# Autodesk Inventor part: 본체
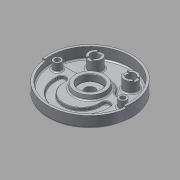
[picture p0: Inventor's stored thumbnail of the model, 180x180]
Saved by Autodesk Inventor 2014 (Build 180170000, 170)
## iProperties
Created: 2015-06
Part Number: 본체
Material: 알루미늄 6061
Document SubType Name: Modeling
Designer: MYHOME
Density: 2.71 g/cm^3
Appearance: 알루미늄 - 평지
Mass: 1071.11 g
Surface Area: 1034.48 cm^2
Volume: 395.243 cm^3
Author: MYHOME
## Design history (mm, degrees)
sketch "스케치1"
  geometry: C1 r 95 at (0, 0); 1 further point
  constraints: 1 centre point, 1 coincident
  dimensions: "d0" = 190 diameter of C1
extrude "돌출1" new body sketch "스케치1" distance "d1" = 32; taper "d2" = 0 deg
sketch "스케치2"
  geometry: C1 r 95 at (0, 0) reference
sketch "스케치3"
  geometry: C1 r 95 at (0, 0) reference; C2 r 90 at (0, 0)
  constraints: 1 centre point, 1 coincident
  dimensions: "d3" = 180 diameter of C2
extrude "돌출2" cut sketch "스케치3" distance "d4" = 25; taper "d5" = 0 deg
sketch "스케치4"
  geometry: C1 r 90 at (0, 0) reference; C2 r 15 at (-40, 52); C3 r 15 at (40, 52)
  constraints: 2 centre point
  dimensions: "d6" = 30 diameter of C2; "d7" = 30 diameter of C3; "d8" = 52 vertical distance of C1.centre C2.centre; "d9" = 52 vertical distance of C1.centre C3.centre; "d10" = 80 distance of C3.centre C2.centre; "d11" = 40 horizontal distance of C1.centre C2.centre
extrude "돌출3" join sketch "스케치4" distance "d12" = 25; taper "d13" = 0 deg
sketch "스케치5"
  geometry: C1 r 15 at (0, 0) reference; C2 r 15 at (80, 0) reference; C3 r 10 at (0, 0); C4 r 10 at (80, 0); 1 further point
  constraints: 2 centre point, 2 coincident
  dimensions: "d14" = 20 diameter of C3; "d15" = 20 diameter of C4
extrude "돌출4" cut sketch "스케치5" stored distance "d16" = 25; taper "d17" = 0 deg
sketch "스케치6"
  geometry: L1 (-6, 13.748)-(-6, -13.748); L2 (6, 13.748)-(6, -13.748); L3 (66.252, 6)-(93.748, 6); L4 (66.252, -6)-(93.748, -6); C1 r 10 at (0, 0) reference; C2 r 10 at (80, 0) reference; A1 r 15 centre (0, 0) between (-6, 13.748) and (6, 13.748) reference; A2 r 15 centre (80, 0) between (66.252, 6) and (66.252, -6) reference; 1 further point
  constraints: 8 end point, 8 point on circle, 2 parallel, 1 perpendicular, 1 vertical
  dimensions: "d18" = 12 distance between parallel lines of L2 L1; "d19" = 6 distance from line of L2 C1.centre; "d20" = 12 distance between parallel lines of L4 L3; "d21" = 6 distance from line of L3 C2.centre
extrude "돌출5" cut sketch "스케치6" distance "d22" = 3; taper "d23" = 0 deg
sketch "스케치7"
  geometry: L1 (-88.566, 16)-(-38.833, 16); L2 (38.833, 16)-(88.566, 16); C1 r 90 at (0, 0) reference; A1 r 90 centre (0, 0) between (-88.566, 16) and (88.566, 16) reference; A2 r 42 centre (0, 0) between (38.833, 16) and (-38.833, 16)
  constraints: 4 end point, 4 point on circle, 2 horizontal, 1 centre point, 1 coincident
  dimensions: "d24" = 16 vertical distance of L2.end A1.centre; "d25" = 84 diameter of A2; "d26" = 16 distance from line of A1.centre L1
extrude "돌출6" join sketch "스케치7" distance "d27" = 7; taper "d28" = 0 deg
sketch "스케치8"
  geometry: C1 r 9 at (-74, 0); C2 r 9 at (74, 0); A1 r 90 centre (0, 0) between (-88.566, 16) and (88.566, 16) reference
  constraints: 2 centre point, 2 horizontal alignment
  dimensions: "d29" = 18 diameter of C1; "d30" = 18 diameter of C2; "d31" = 148 distance of C2.centre C1.centre; "d32" = 74 distance of C2.centre A1.centre
extrude "돌출7" join sketch "스케치8" distance "d33" = 14; taper "d34" = 0 deg
sketch "스케치9"
  geometry: C1 r 35 at (0, 0); A1 r 42 centre (0, 0) between (38.833, 16) and (-38.833, 16) reference
  constraints: 1 centre point, 1 coincident
  dimensions: "d35" = 70 diameter of C1
extrude "돌출8" join sketch "스케치9" distance "d36" = 10; taper "d37" = -10 deg
sketch "스케치10"
  geometry: C1 r 33.237 at (0, 0) reference; C2 r 25 at (0, 0)
  constraints: 1 centre point, 1 coincident
  dimensions: "d38" = 50 diameter of C2
extrude "돌출9" cut sketch "스케치10" distance "d39" = 15; taper "d40" = 0 deg
sketch "스케치11"
  geometry: C1 r 25 at (0, 0) reference; C2 r 11.5 at (0, 0)
  constraints: 1 centre point, 1 coincident
  dimensions: "d41" = 23 diameter of C2
extrude "돌출10" cut sketch "스케치11" stored distance "d42" = 15; taper "d43" = 0 deg
sketch "스케치15"
  geometry: L1 (-38.833, 16)-(-88.566, 16) reference; L2 (-59, -14)-(-59, -19); L3 (-41, -14)-(-41, -19); L4 (41, -19)-(41, -14); L5 (59, -14)-(59, -19); C1 r 35 at (0, 0) reference; A1 r 9 centre (-50, -14) between (-41, -14) and (-59, -14); A2 r 9 centre (50, -14) between (59, -14) and (41, -14); A3 r 41 centre (0, -19) between (-40.992, -18.18) and (41, -19); A4 r 59 centre (0, -19) between (-58.988, -17.82) and (59, -19); 1 further point
  constraints: 10 point on circle, 8 end point, 4 centre point, 4 tangent, 3 parallel, 1 coincident, 1 perpendicular, 1 vertical alignment
  dimensions: "d64" = 9 radius of A1; "d65" = 9 radius of A2; "d66" = 14 vertical distance of C1.centre A1.centre; "d67" = 14 vertical distance of C1.centre A2.centre; "d68" = 100 distance of A2.centre A1.centre; "d69" = 50 horizontal distance of A1.centre C1.centre; "d70" = 19 distance of point (0, -19) C1.centre; "d72" = 59 radius of A4; "d73" = 41 radius of A3
extrude "돌출12" cut sketch "스케치15" distance "d74" = 7; taper "d75" = 0 deg
fillet "모깎기1" dims "d76" = 1
sketch "스케치16"
  geometry: C1 r 9 at (0, 0) reference; C2 r 9 at (148, 0) reference; C3 r 5.5 at (0, 0); C4 r 5.5 at (148, 0); 1 further point
  constraints: 2 centre point, 2 coincident
  dimensions: "d77" = 11 diameter of C3; "d78" = 11 diameter of C4
extrude "돌출13" cut sketch "스케치16" stored distance "d79" = 7; taper "d80" = 0 deg
sketch "스케치17"
  geometry: C1 r 5.5 at (74, 0) reference; C2 r 5.5 at (-74, 0) reference
hole "구멍1" sketch "스케치17" at (-74, 0), (74, 0) diameter "d81" = 18; stored, may be unused: countersink angle "d85" = 90 deg, drill point angle "d87" = 0 deg; dims "d82" = 6, "d83" = 4, "d84" = 2, "d86" = 11
fillet "모깎기2" dims "d88" = 10
node "작업 평면1"
sketch "스케치20"
  geometry: L1 (0, 0)-(-89.124, -12.526); L2 (0, 0)-(89.124, -12.526); L3 (-95, 0)-(95, 0); L4 (89.124, -12.526)-(94.075, -13.221); L5 (-89.124, -12.526)-(-94.075, -13.221); A1 r 90 centre (0, 0) between (89.124, -12.526) and (-89.124, -12.526) reference; A2 r 95 centre (0, 0) between (-94.075, -13.221) and (-95, 0) reference
  constraints: 10 end point, 6 point on circle, 2 collinear, 1 horizontal, 1 midpoint
  dimensions: "d97" = 8 deg angle of L2 L3; "d98" = 8 deg angle of L1 L3
extrude "돌출14" cut sketch "스케치20" distance "d99" = 5; taper "d100" = 0 deg
fillet "모깎기3" dims "d101" = 3
fillet "모깎기4" dims "d102" = 3
fillet "모깎기5" dims "d103" = 3
fillet "모깎기6" dims "d104" = 3
fillet "모깎기7" dims "d105" = 3
fillet "모깎기8" dims "d106" = 3
fillet "모깎기9" dims "d107" = 5
fillet "모깎기10" dims "d108" = 0.3
fillet "모깎기11" dims "d112" = 3
sketch "스케치21"
  geometry: C1 r 90 at (0, 0) reference; C2 r 68 at (0, 0)
  constraints: 1 centre point, 1 coincident, 1 other
  dimensions: "d114" = 136 diameter of C2
feature "엠보싱1" sketch "스케치21" dims "d0" = 190, "d12" = 25, "d13" = 0, "d115" = 0.5, "d116" = 0
fillet "모깎기12" dims "d117" = 3
chamfer "모따기2" distance "d119" = 1; stored, may be unused: second distance "d120" = 2, angle "d121" = 45 deg
chamfer "모따기3" distance "d122" = 1; stored, may be unused: second distance "d123" = 2, angle "d124" = 45 deg
sketch "스케치22"
  geometry: C1 r 11.5 at (0, 0) reference; C2 r 26 at (0, 0)
  constraints: 1 centre point, 1 coincident
  dimensions: "d125" = 52 diameter of C2
extrude "돌출15" join sketch "스케치22" distance "d126" = 12; taper "d127" = -15 deg
sketch "스케치23"
  geometry: C1 r 22.785 at (0, 0) reference; C2 r 11.5 at (0, 0)
  constraints: 1 centre point, 1 coincident
  dimensions: "d128" = 23 diameter of C2
extrude "돌출16" cut sketch "스케치23" stored distance "d129" = 12; taper "d130" = 0 deg
fillet "모깎기14" dims "d131" = 3
chamfer "모따기4" distance "d132" = 1; stored, may be unused: second distance "d133" = 2, angle "d134" = 45 deg
sketch "스케치24"
  geometry: C1 r 5.5 at (0, 0) reference; C2 r 9 at (0, 0) reference; C3 r 9 at (148, 0) reference; C4 r 5.5 at (148, 0) reference; 1 further point
extrude "돌출17" join sketch "스케치24" stored distance "d135" = 12; taper "d136" = 0 deg
node "솔리드1"
node "투영된 루프1"
node "투영된 루프2"
other parameters: "d47" = 59, "d49" = 41, "d51" = 59, "d52" = 19, "d54" = 5, "d95" = 27
